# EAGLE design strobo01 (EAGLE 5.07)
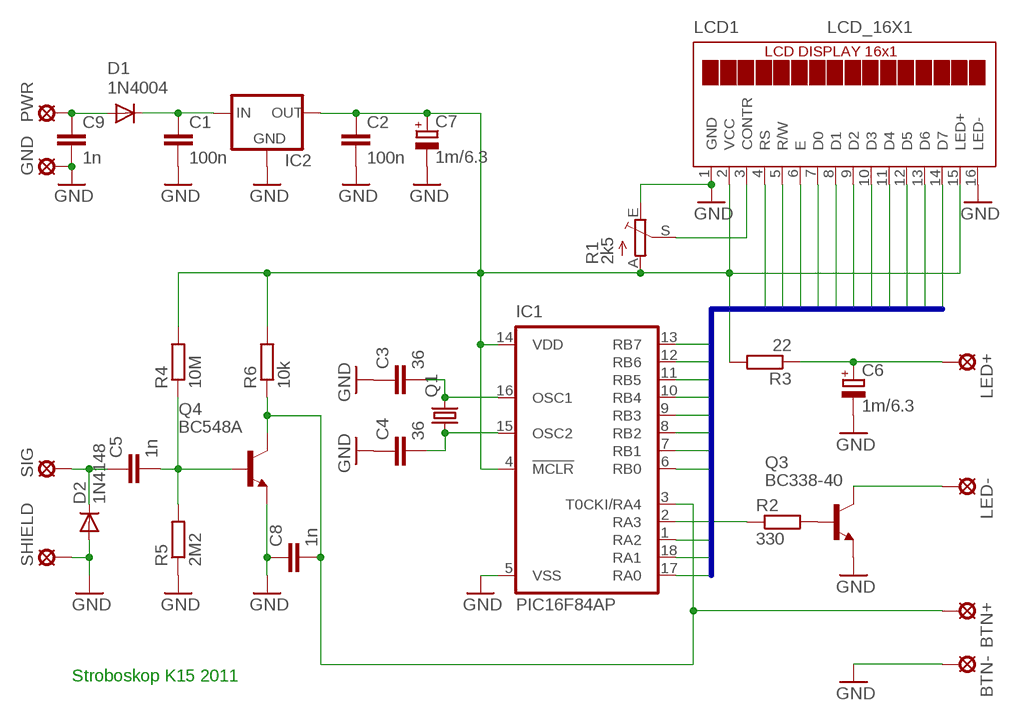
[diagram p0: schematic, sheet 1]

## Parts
BTN+  SE11  [SE11]
BTN-  SE11  [SE11]
C1  100n  C-EU050-024X044  [C050-024X044]
C2  100n  C-EU050-024X044  [C050-024X044]
C3  36  C-EU050-024X044  [C050-024X044]
C4  36  C-EU050-024X044  [C050-024X044]
C5  1n  C-EU050-024X044  [C050-024X044]
C6  1m/6.3  CPOL-EUE5-8.5  [E5-8,5]
C7  1m/6.3  CPOL-EUE5-8.5  [E5-8,5]
C8  1n  C-EU050-024X044  [C050-024X044]
C9  1n  C-EU050-024X044  [C050-024X044]
D1  1N4004  [DO41-10]
D2  1N4148  1N4004  [DO41-10]
GND  SE11  [SE11]
IC1  PIC16F84AP  [DIL18]
IC2  78XXL  [78XXL]
LCD1  LCD_16X1  [LCD_16X1]
LED+  SE11  [SE11]
LED-  SE11  [SE11]
PWR  SE11  [SE11]
Q1  CRYSTALHC49U70  [HC49U70]
Q3  BC338-40  [TO92-EBC]
Q4  BC548A  [TO92-EBC]
R1  2k5  TRIM_EU-LI10  [LI10]
R2  330  R-EU_0207/10  [0207/10]
R3  22  R-EU_0207/10  [0207/10]
R4  10M  R-EU_0207/10  [0207/10]
R5  2M2  R-EU_0207/10  [0207/10]
R6  10k  R-EU_0207/10  [0207/10]
SHIELD  SE11  [SE11]
SIG  SE11  [SE11]

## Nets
GND: BTN-.MP C1.2 C2.2 C3.1 C4.1 C6.- C7.- C8.1 C9.2 D2.A GND.MP IC1.5(VSS) IC2.GND LCD1.1(GND) LCD1.16(LED-) Q3.E Q4.E R1.E R5.1 SHIELD.MP
LCD.D0: IC1.6(RB0) LCD1.7(D0)
LCD.D1: IC1.7(RB1) LCD1.8(D1)
LCD.D2: IC1.8(RB2) LCD1.9(D2)
LCD.D3: IC1.9(RB3) LCD1.10(D3)
LCD.D4: IC1.10(RB4) LCD1.11(D4)
LCD.D5: IC1.11(RB5) LCD1.12(D5)
LCD.D6: IC1.12(RB6) LCD1.13(D6)
LCD.D7: IC1.13(RB7) LCD1.14(D7)
LCD.E: IC1.17(RA0) LCD1.6(E)
LCD.RS: IC1.1(RA2) LCD1.4(RS)
LCD.RW: IC1.18(RA1) LCD1.5(R/W)
N$1: C3.2 IC1.16(OSC1) Q1.2
N$2: C4.2 IC1.15(OSC2) Q1.1
N$3: C2.1 C7.+ IC1.4(!MCLR) IC1.14(VDD) IC2.OUT LCD1.2(VCC) LCD1.15(LED+) R1.A R3.2 R4.2 R6.2
N$4: C1.1 D1.C IC2.IN
N$5: C9.1 D1.A PWR.MP
N$6: LCD1.3(CONTR) R1.S
N$7: Q3.B R2.2
N$8: IC1.2(RA3) R2.1
N$9: C6.+ LED+.MP R3.1
N$10: LED-.MP Q3.C
N$11: C5.2 Q4.B R4.1 R5.2
N$12: BTN+.MP C8.2 IC1.3(T0CKI/RA4) Q4.C R6.1
N$13: C5.1 D2.C SIG.MP

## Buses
LCD

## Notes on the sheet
- Stroboskop K15 2011

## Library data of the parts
BTN+ BTN- GND LED+ LED- PWR SHIELD SIG = solpad:SE11: SOLDER PAD
C1-C5 C8 C9 = rcl:C-EU: CAPACITOR, European symbol
C6 C7 = rcl:CPOL-EU: POLARIZED CAPACITOR, European symbol
D1 D2 = diode:1N4004: DIODE
IC1 = microchip:PIC16F8*: MICROCONTROLLER 8-Bit PIC16F8X Family - CMOS Flash/EEPROM Pin Compatible : PIC16F83, PIC16CR83, PIC16F84A, PIC16CR84 see also PIC16C*
IC2 = v-reg:78XXL: VOLTAGE REGULATOR
LCD1 = lcd:LCD_16X1
Q1 = crystal:CRYSTAL: CRYSTAL
Q3 = transistor-npn:BC338*: NPN Transistor
Q4 = transistor-npn:BC548*: NPN Transistor
R1 = pot:TRIM_EU-: POTENTIOMETER
R2-R6 = rcl:R-EU_: RESISTOR, European symbol

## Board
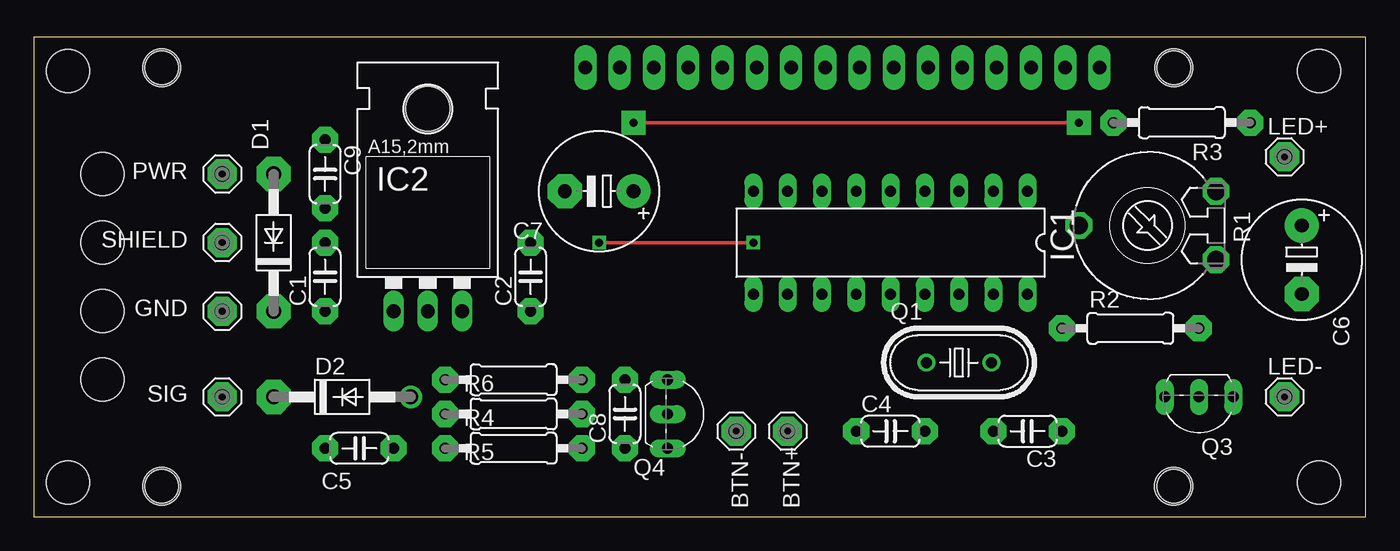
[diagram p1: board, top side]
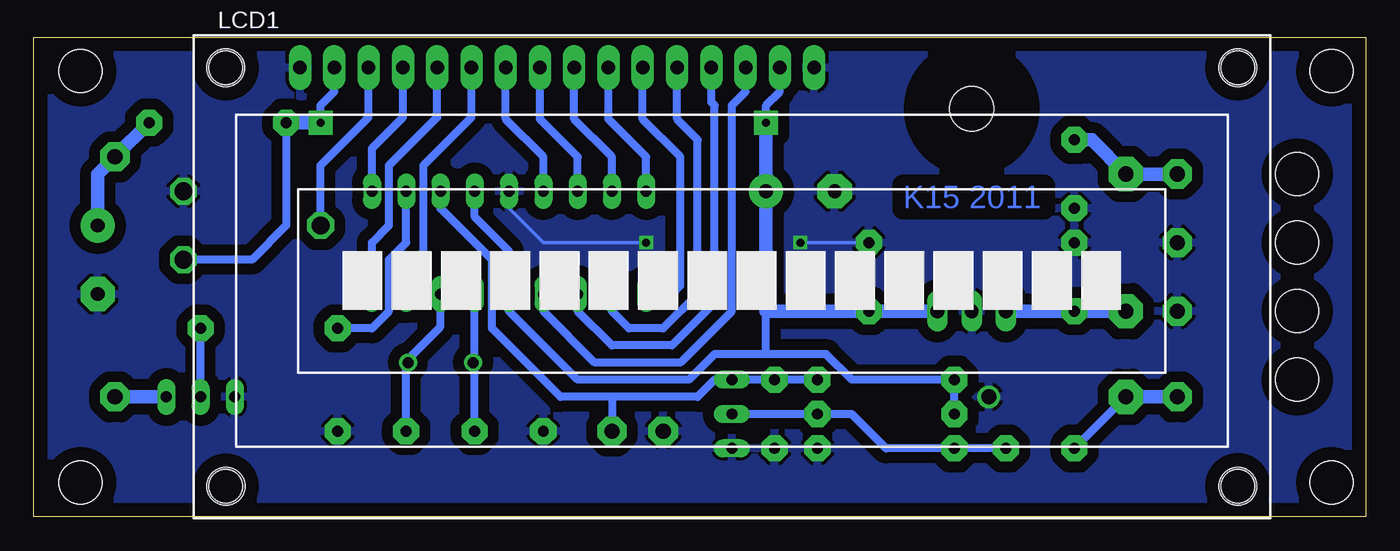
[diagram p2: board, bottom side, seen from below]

Size 98.73 x 35.55 mm. Coordinates in mm from the lower left corner, seen from the top.
Outline: 0,0 98.73,0 98.73,35.55 0,35.55 0,0
Copper layers (1*16): Top 0.035mm / dielectric 1.5mm / Bottom 0.035mm
Design rules "default": minimum track width 10mil, minimum drill 24mil, track to track 8mil, track to pad 8mil, pad to pad 8mil, via to via 8mil, smd to smd 8mil, copper to edge 40mil, drill to drill 8mil, minimum pad ring 10mil, minimum via ring 8mil, stop-mask expansion 4mil, vias tented up to drill 0mil, thermal gap 10mil
Holes 2.8 mm at 9.48,2.28 9.49,33.28 84.49,33.28 84.49,2.28
Holes 3.2 mm at 2.54,33.02 2.54,2.54 95.25,33.02 95.25,2.54 5.08,25.4 5.08,20.32 5.08,15.24 5.08,10.16

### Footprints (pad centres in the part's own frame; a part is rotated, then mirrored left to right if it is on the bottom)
SE11 = drill 1.118 pad 2.159 octagon: MP 0,0
C050-024X044 = drill 0.813 pad 1.93 octagon: 1 -2.54,0; 2 2.54,0
E5-8,5 = drill 1.016 pad 2.54 round: + -2.54,0 | drill 1.016 pad 2.54 octagon: - 2.54,0
DO41-10 = drill 1.118 round: A 5.08,0; C -5.08,0
DIL18 = drill 0.813 long: 1 -10.16,-3.81; 2 -7.62,-3.81; 3 -5.08,-3.81; 4 -2.54,-3.81; 5 0,-3.81; 6 2.54,-3.81; 7 5.08,-3.81; 8 7.62,-3.81; 9 10.16,-3.81; 10 10.16,3.81; 11 7.62,3.81; 12 5.08,3.81; 13 2.54,3.81; 14 0,3.81; 15 -2.54,3.81; 16 -5.08,3.81; 17 -7.62,3.81; 18 -10.16,3.81
78XXL = drill 1.016 long: GND 0,-3.81; IN -2.54,-3.81; OUT 2.54,-3.81 | hole 3.302: 0,11.176
LCD_16X1 = drill 1 pad 1.676 long: 1 -32,15.5; 2 -29.46,15.5; 3 -26.92,15.5; 4 -24.38,15.5; 5 -21.84,15.5; 6 -19.3,15.5; 7 -16.76,15.5; 8 -14.22,15.5; 9 -11.68,15.5; 10 -9.14,15.5; 11 -6.6,15.5; 12 -4.06,15.5; 13 -1.52,15.5; 14 1.02,15.5; 15 3.56,15.5; 16 6.1,15.5 | hole 2.5: -37.5,-15.5; 37.5,-15.5; -37.5,15.5; 37.5,15.5
HC49U70 = drill 0.813 round: 1 -2.413,0; 2 2.413,0
TO92-EBC = drill 0.813 long: B 0,-1.27; C -2.54,-1.27; E 2.54,-1.27
LI10 = drill 1.321 octagon: A -2.54,-5.08; E 2.54,-5.08; S 0,5.08
0207/10 = drill 0.813 pad 1.93 octagon: 1 -5.08,0; 2 5.08,0

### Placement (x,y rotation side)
BTN+  55.88,6.35 0 top
BTN-  52.07,6.35 0 top
C1  21.59,17.78 90 top
C2  36.83,17.78 90 top
C3  73.66,6.35 180 top
C4  63.5,6.35 0 top
C5  24.13,5.08 0 top
C6  93.98,19.05 270 top
C7  41.91,24.13 180 top
C8  43.81,7.62 90 top
C9  21.59,25.4 270 top
D1  17.78,20.32 90 top
D2  22.86,8.89 0 top
GND  13.97,15.24 0 top
IC1  63.5,20.32 180 top
IC2  29.21,19.05 0 top
LCD1  46.99,17.78 0 bottom
LED+  92.71,26.67 0 top
LED-  92.71,8.89 0 top
PWR  13.97,25.4 0 top
Q1  68.58,11.43 0 top
Q3  86.36,7.62 180 top
Q4  48.26,7.62 270 top
R1  82.55,21.59 90 top
R2  81.28,13.97 0 top
R3  85.09,29.21 180 top
R4  35.56,7.62 180 top
R5  35.56,5.08 180 top
R6  35.56,10.16 180 top
SHIELD  13.97,20.32 0 top
SIG  13.97,8.89 0 top

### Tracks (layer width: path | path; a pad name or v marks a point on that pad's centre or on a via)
GND  (via drill 0.6)
  Top 0.254: v41.91,20.32 v53.34,20.32
  Bottom 0.254: C2.2 v41.91,20.32 | v53.34,20.32 60.96,20.32 63.5,22.86 IC1.5
  pour Bottom (isolate 0.813): 0,35.56 100.33,35.56 100.33,0 0,0
LCD.D0
  Bottom 0.61: IC1.6 60.96,26.67 63.75,29.46 LCD1.7
LCD.D1
  Bottom 0.61: IC1.7 58.42,26.67 61.21,29.46 LCD1.8
LCD.D2
  Bottom 0.61: IC1.8 55.88,26.67 58.67,29.46 LCD1.9
LCD.D3
  Bottom 0.61: IC1.9 53.34,26.67 56.13,29.46 LCD1.10
LCD.D4
  Bottom 0.61: IC1.10 51.44,16.51 50.8,17.14 50.8,26.67 53.59,29.46 LCD1.11
LCD.D5
  Bottom 0.61: IC1.11 55.88,15.24 54.61,13.97 52.07,13.97 49.53,16.51 49.53,27.94 51.05,29.46 LCD1.12
LCD.D6
  Bottom 0.61: IC1.12 58.42,15.24 55.88,12.7 51.44,12.7 48.26,15.88 48.26,30.48 48.51,30.73 LCD1.13
LCD.D7
  Bottom 0.61: IC1.13 60.96,15.24 57.15,11.43 50.8,11.43 46.99,15.24 46.99,30.48 45.97,31.5 LCD1.14
LCD.E
  Bottom 0.61: IC1.17 71.12,17.78 69.85,19.05 69.85,26.04 66.29,29.59 LCD1.6
LCD.RS
  Bottom 0.61: IC1.1 73.66,27.3 71.37,29.59 LCD1.4
LCD.RW
  Bottom 0.61: IC1.18 73.66,20.32 72.39,21.59 72.39,26.04 68.83,29.59 LCD1.5
N$1
  Bottom 0.61: IC1.16 68.58,14.1 70.99,11.68 Q1.2 71.12,11.3 C3.2
N$2
  Bottom 0.61: IC1.15 66.04,11.43 Q1.1 66.04,11.3 C4.2
N$3  (via drill 0.6 pad 1.78)
  Top 0.254: v44.45,29.21 v77.47,29.21
  Bottom 0.61: R4.2 R6.2 38.1,10.16 40.01,12.06 44.45,12.06 | IC1.4 66.04,22.23 63.5,19.68 IC1.14 63.5,15.24 58.42,10.16 50.16,10.16 48.26,12.06 44.45,12.06 | v77.47,29.21 77.47,30.48 76.45,31.5 LCD1.2 | R1.A 82.55,19.05 80.01,21.59 R3.2 | LCD1.15 43.43,31.5 44.45,30.48 v44.45,29.21 | 44.45,12.06 44.45,15.24
  Bottom 1.016: IC2.OUT C2.1 44.45,15.24 C7.+ v44.45,29.21 | v77.47,29.21 R3.2
N$4
  Bottom 1.016: D1.C C1.1 IC2.IN
N$5
  Bottom 1.016: PWR.MP D1.A 20.32,27.94 C9.1
N$6
  Bottom 0.61: LCD1.3 73.91,29.59 77.47,26.04 R1.S
N$7
  Bottom 0.61: Q3.B R2.2
N$8
  Bottom 0.61: R2.1 73.66,13.97 72.39,15.24 72.39,19.05 71.12,20.32 IC1.2
N$9
  Bottom 1.016: R3.1 LED+.MP 93.98,25.4 C6.+
N$10
  Bottom 1.016: Q3.C LED-.MP
N$11
  Bottom 0.61: C5.2 R5.2 35.56,5.08 38.1,7.62 R4.1 Q4.B
N$12
  Bottom 0.61: R6.1 C8.2 Q4.C 48.26,10.16 49.53,8.89 55.88,8.89 | IC1.3 68.58,22.86 64.77,19.05 64.77,13.97 59.69,8.89 55.88,8.89 | 55.88,8.89 BTN+.MP
N$13
  Bottom 0.61: D2.C C5.1
  Bottom 1.016: SIG.MP D2.C
N$14  (via drill 0.6 pad 2.54)
  other vias: 17.78,25.4
N$15  (via drill 0.6 pad 2.54)
  other vias: 17.78,15.24
N$17  (via drill 0.6 pad 2.54)
  other vias: 17.78,8.89

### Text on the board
Bottom: K15 2011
